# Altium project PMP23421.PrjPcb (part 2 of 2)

## Sheet PMP23421_buffer.SchDoc
size 431 x 279 mm; Date: Not shown in title block; ApprovedBy: Not shown in title block; CheckedBy: Not shown in title block; Author: Not shown in title block; CompanyName: Not shown in title block; Engineer: Not shown in title block; Organization: Not shown in title block; Address1: Not shown in title block; Address2: Not shown in title block; Address3: Not shown in title block; Address4: Not shown in title block; DocumentNumber: 3; Revision: Use project parameter SCH_Rev; SheetNumber: 3; SheetTotal: 3; PageSetup: Record=PageOptions¦CenterHorizontal=True¦CenterVertical=True¦PrintScale=1.00¦XCorrection=1.00¦YCorrection=1.00¦PrintKind=0¦BorderSize=5000000¦LeftOffset=0¦BottomOffset=0¦Orientation=2¦PaperLength=1000¦PaperWidth=1000¦Scale=100¦PaperSource=15¦PrintQuality=600¦MediaType=1¦DitherType=10¦PaperKind=Letter¦PrintScaleMode=1
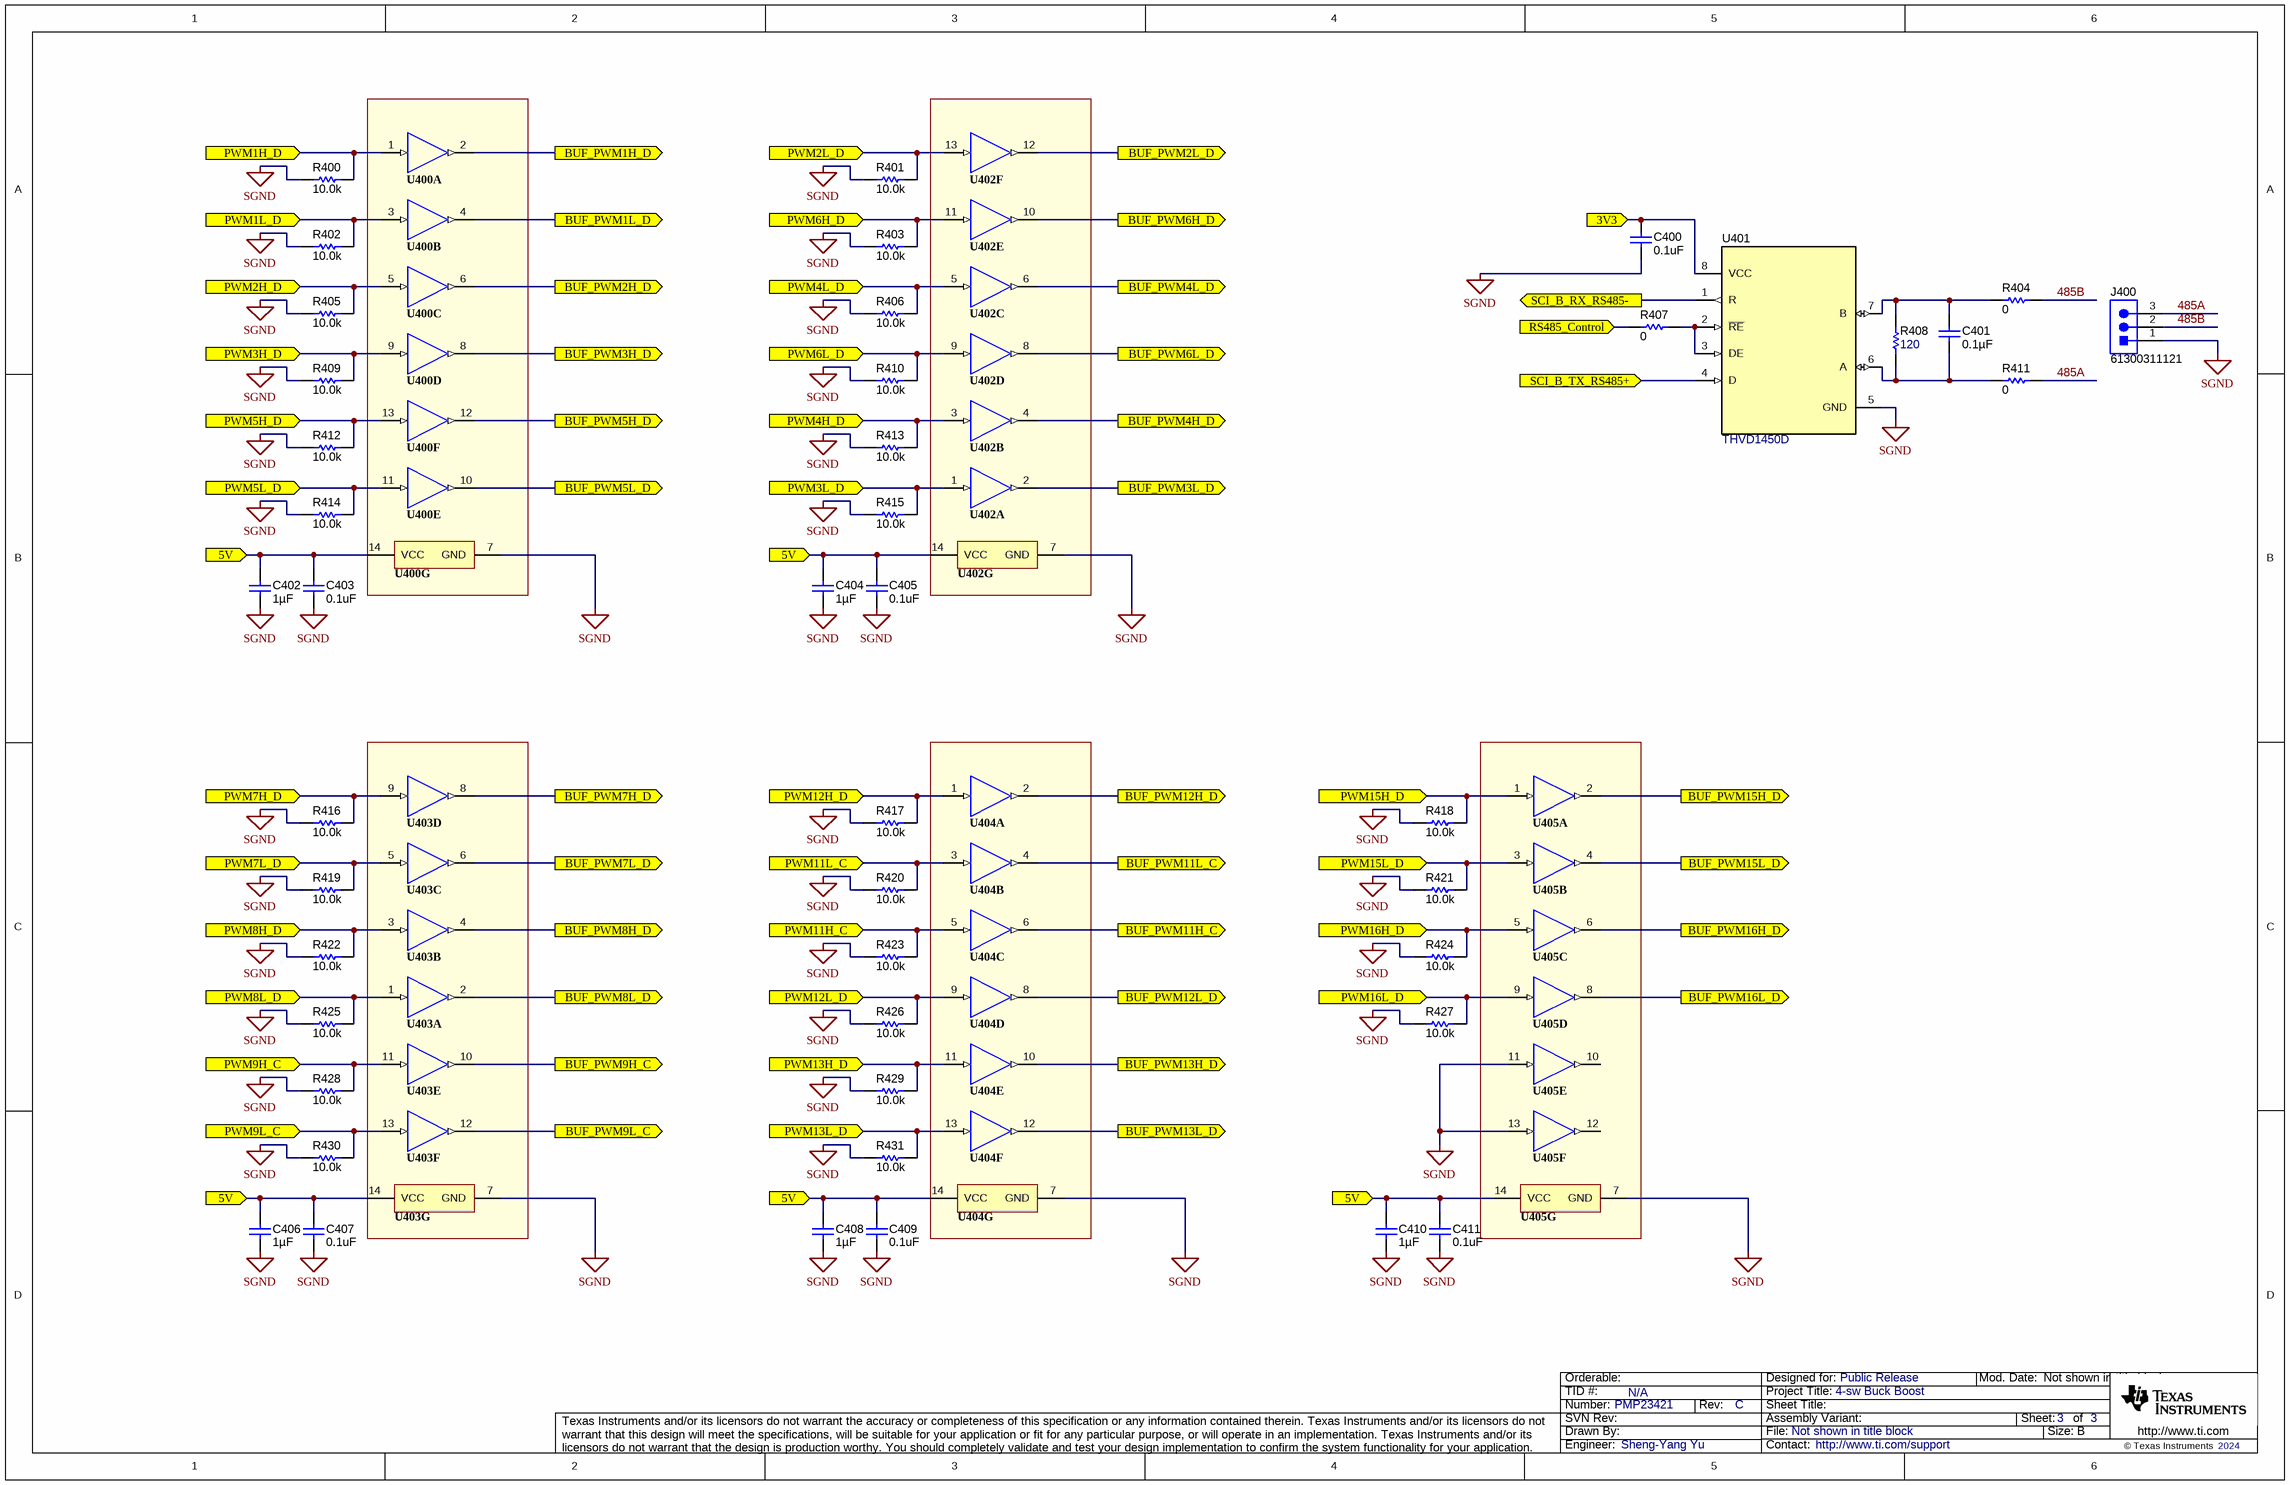
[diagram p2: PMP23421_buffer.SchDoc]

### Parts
(Parts that share a designator on the sheet are numbered #1, #2 ... from top to bottom, then left to right.)
C400  ValueDisplayed: 0.1uF  [0402]  (hidden comment: GRM155R70J104KA01D)
C401  ValueDisplayed: 0.1µF  [1206]  (hidden comment: 12061C104JAT2A)
C402  ValueDisplayed: 1µF  [0603]  (hidden comment: C1608X7R1C105K080AC)
C403  ValueDisplayed: 0.1uF  [0402]  (hidden comment: GRM155R70J104KA01D)
C404  ValueDisplayed: 1µF  [0603]  (hidden comment: C1608X7R1C105K080AC)
C405  ValueDisplayed: 0.1uF  [0402]  (hidden comment: GRM155R70J104KA01D)
C406  ValueDisplayed: 1µF  [0603]  (hidden comment: C1608X7R1C105K080AC)
C407  ValueDisplayed: 0.1uF  [0402]  (hidden comment: GRM155R70J104KA01D)
C408  ValueDisplayed: 1µF  [0603]  (hidden comment: C1608X7R1C105K080AC)
C409  ValueDisplayed: 0.1uF  [0402]  (hidden comment: GRM155R70J104KA01D)
C410  ValueDisplayed: 1µF  [0603]  (hidden comment: C1608X7R1C105K080AC)
C411  ValueDisplayed: 0.1uF  [0402]  (hidden comment: GRM155R70J104KA01D)
J400  61300311121  [WURTH_61300311121]
R400  ValueDisplayed: 10.0k  [0603]  (hidden comment: RCG060310K0FKEA)
R401  ValueDisplayed: 10.0k  [0603]  (hidden comment: RCG060310K0FKEA)
R402  ValueDisplayed: 10.0k  [0603]  (hidden comment: RCG060310K0FKEA)
R403  ValueDisplayed: 10.0k  [0603]  (hidden comment: RCG060310K0FKEA)
R404  ValueDisplayed: 0  [0603]  (hidden comment: RC0603JR-070RL)
R405  ValueDisplayed: 10.0k  [0603]  (hidden comment: RCG060310K0FKEA)
R406  ValueDisplayed: 10.0k  [0603]  (hidden comment: RCG060310K0FKEA)
R407  ValueDisplayed: 0  [0603]  (hidden comment: RC0603JR-070RL)
R408  ValueDisplayed: 120  [0603]  (hidden comment: RC0603FR-07120RL)
R409  ValueDisplayed: 10.0k  [0603]  (hidden comment: RCG060310K0FKEA)
R410  ValueDisplayed: 10.0k  [0603]  (hidden comment: RCG060310K0FKEA)
R411  ValueDisplayed: 0  [0603]  (hidden comment: RC0603JR-070RL)
R412  ValueDisplayed: 10.0k  [0603]  (hidden comment: RCG060310K0FKEA)
R413  ValueDisplayed: 10.0k  [0603]  (hidden comment: RCG060310K0FKEA)
R414  ValueDisplayed: 10.0k  [0603]  (hidden comment: RCG060310K0FKEA)
R415  ValueDisplayed: 10.0k  [0603]  (hidden comment: RCG060310K0FKEA)
R416  ValueDisplayed: 10.0k  [0603]  (hidden comment: RCG060310K0FKEA)
R417  ValueDisplayed: 10.0k  [0603]  (hidden comment: RCG060310K0FKEA)
R418  ValueDisplayed: 10.0k  [0603]  (hidden comment: RCG060310K0FKEA)
R419  ValueDisplayed: 10.0k  [0603]  (hidden comment: RCG060310K0FKEA)
R420  ValueDisplayed: 10.0k  [0603]  (hidden comment: RCG060310K0FKEA)
R421  ValueDisplayed: 10.0k  [0603]  (hidden comment: RCG060310K0FKEA)
R422  ValueDisplayed: 10.0k  [0603]  (hidden comment: RCG060310K0FKEA)
R423  ValueDisplayed: 10.0k  [0603]  (hidden comment: RCG060310K0FKEA)
R424  ValueDisplayed: 10.0k  [0603]  (hidden comment: RCG060310K0FKEA)
R425  ValueDisplayed: 10.0k  [0603]  (hidden comment: RCG060310K0FKEA)
R426  ValueDisplayed: 10.0k  [0603]  (hidden comment: RCG060310K0FKEA)
R427  ValueDisplayed: 10.0k  [0603]  (hidden comment: RCG060310K0FKEA)
R428  ValueDisplayed: 10.0k  [0603]  (hidden comment: RCG060310K0FKEA)
R429  ValueDisplayed: 10.0k  [0603]  (hidden comment: RCG060310K0FKEA)
R430  ValueDisplayed: 10.0k  [0603]  (hidden comment: RCG060310K0FKEA)
R431  ValueDisplayed: 10.0k  [0603]  (hidden comment: RCG060310K0FKEA)
U400  SN74ALS1034D  [D0014A_L]  (value not drawn)  (parts A,B,C,D,E,F,G of 7)
U401  THVD1450D  [D0008A_N]
U402#1  SN74ALS1034D  [D0014A_L]  (value not drawn)  (part F of 7)
U402#2  SN74ALS1034D  [D0014A_L]  (value not drawn)  (parts A,B,C,D,E,G of 7)
U403#1  SN74ALS1034D  [D0014A_L]  (value not drawn)  (parts B,F of 7)
U403#2  SN74ALS1034D  [D0014A_L]  (value not drawn)  (parts A,C,D,E,G of 7)
U404#1  SN74ALS1034D  [D0014A_L]  (value not drawn)  (parts B,E of 7)
U404#2  SN74ALS1034D  [D0014A_L]  (value not drawn)  (parts A,C,D,F,G of 7)
U405#1  SN74ALS1034D  [D0014A_L]  (value not drawn)  (parts B,C,E,F of 7)
U405#2  SN74ALS1034D  [D0014A_L]  (value not drawn)  (parts A,D,G of 7)

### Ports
3V3 (in), 5V (in), BUF_PWM1H_D (out), BUF_PWM1L_D (out), BUF_PWM2H_D (out), BUF_PWM2L_D (out), BUF_PWM3H_D (out), BUF_PWM3L_D (out), BUF_PWM4H_D (out), BUF_PWM4L_D (out), BUF_PWM5H_D (out), BUF_PWM5L_D (out), BUF_PWM6H_D (out), BUF_PWM6L_D (out), BUF_PWM7H_D (out), BUF_PWM7L_D (out), BUF_PWM8H_D (out), BUF_PWM8L_D (out), BUF_PWM9H_C (out), BUF_PWM9L_C (out), BUF_PWM11H_C (out), BUF_PWM11L_C (out), BUF_PWM12H_D (out), BUF_PWM12L_D (out), BUF_PWM13H_D (out), BUF_PWM13L_D (out), BUF_PWM15H_D (out), BUF_PWM15L_D (out), BUF_PWM16H_D (out), BUF_PWM16L_D (out), PWM1H_D (in), PWM1L_D (in), PWM2H_D (in), PWM2L_D (in), PWM3H_D (in), PWM3L_D (in), PWM4H_D (in), PWM4L_D (in), PWM5H_D (in), PWM5L_D (in), PWM6H_D (in), PWM6L_D (in), PWM7H_D (in), PWM7L_D (in), PWM8H_D (in), PWM8L_D (in), PWM9H_C (in), PWM9L_C (in), PWM11H_C (in), PWM11L_C (in), PWM12H_D (in), PWM12L_D (in), PWM13H_D (in), PWM13L_D (in), PWM15H_D (in), PWM15L_D (in), PWM16H_D (in), PWM16L_D (in), RS485_Control (in), SCI_B_RX_RS485- (out), SCI_B_TX_RS485+ (in)

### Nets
SGND: C400.1 C402.2 C403.1 C404.2 C405.1 C406.2 C407.1 C408.2 C409.1 C410.2 C411.1 J400.1 R400.1 R401.1 R402.1 R403.1 R405.1 R406.1 R409.1 R410.1 R412.1 R413.1 R414.1 R415.1 R416.1 R417.1 R418.1 R419.1 R420.1 R421.1 R422.1 R423.1 R424.1 R425.1 R426.1 R427.1 R428.1 R429.1 R430.1 R431.1 U400.7(GND) U401.5(GND) U402#2.7(GND) U403#2.7(GND) U404#2.7(GND) U405#1.11(5A) U405#1.13(6A) U405#2.7(GND)
3V3: C400.2 U401.8(VCC) ; port 3V3
5V: C402.1 C403.2 C404.1 C405.2 C406.1 C407.2 C408.1 C409.2 C410.1 C411.2 U400.14(VCC) U402#2.14(VCC) U403#2.14(VCC) U404#2.14(VCC) U405#2.14(VCC) ; port 5V
485A: J400.3 R411.2
485B: J400.2 R404.2
BUF_PWM1H_D: U400.2(1Y) ; port BUF_PWM1H_D
BUF_PWM1L_D: U400.4(2Y) ; port BUF_PWM1L_D
BUF_PWM2H_D: U400.6(3Y) ; port BUF_PWM2H_D
BUF_PWM2L_D: U402#1.12(6Y) ; port BUF_PWM2L_D
BUF_PWM3H_D: U400.8(4Y) ; port BUF_PWM3H_D
BUF_PWM3L_D: U402#2.2(1Y) ; port BUF_PWM3L_D
BUF_PWM4H_D: U402#2.4(2Y) ; port BUF_PWM4H_D
BUF_PWM4L_D: U402#2.6(3Y) ; port BUF_PWM4L_D
BUF_PWM5H_D: U400.12(6Y) ; port BUF_PWM5H_D
BUF_PWM5L_D: U400.10(5Y) ; port BUF_PWM5L_D
BUF_PWM6H_D: U402#2.10(5Y) ; port BUF_PWM6H_D
BUF_PWM6L_D: U402#2.8(4Y) ; port BUF_PWM6L_D
BUF_PWM7H_D: U403#2.8(4Y) ; port BUF_PWM7H_D
BUF_PWM7L_D: U403#2.6(3Y) ; port BUF_PWM7L_D
BUF_PWM8H_D: U403#1.4(2Y) ; port BUF_PWM8H_D
BUF_PWM8L_D: U403#2.2(1Y) ; port BUF_PWM8L_D
BUF_PWM9H_C: U403#2.10(5Y) ; port BUF_PWM9H_C
BUF_PWM9L_C: U403#1.12(6Y) ; port BUF_PWM9L_C
BUF_PWM11H_C: U404#2.6(3Y) ; port BUF_PWM11H_C
BUF_PWM11L_C: U404#1.4(2Y) ; port BUF_PWM11L_C
BUF_PWM12H_D: U404#2.2(1Y) ; port BUF_PWM12H_D
BUF_PWM12L_D: U404#2.8(4Y) ; port BUF_PWM12L_D
BUF_PWM13H_D: U404#1.10(5Y) ; port BUF_PWM13H_D
BUF_PWM13L_D: U404#2.12(6Y) ; port BUF_PWM13L_D
BUF_PWM15H_D: U405#2.2(1Y) ; port BUF_PWM15H_D
BUF_PWM15L_D: U405#1.4(2Y) ; port BUF_PWM15L_D
BUF_PWM16H_D: U405#1.6(3Y) ; port BUF_PWM16H_D
BUF_PWM16L_D: U405#2.8(4Y) ; port BUF_PWM16L_D
PWM1H_D: R400.2 U400.1(1A) ; port PWM1H_D
PWM1L_D: R402.2 U400.3(2A) ; port PWM1L_D
PWM2H_D: R405.2 U400.5(3A) ; port PWM2H_D
PWM2L_D: R401.2 U402#1.13(6A) ; port PWM2L_D
PWM3H_D: R409.2 U400.9(4A) ; port PWM3H_D
PWM3L_D: R415.2 U402#2.1(1A) ; port PWM3L_D
PWM4H_D: R413.2 U402#2.3(2A) ; port PWM4H_D
PWM4L_D: R406.2 U402#2.5(3A) ; port PWM4L_D
PWM5H_D: R412.2 U400.13(6A) ; port PWM5H_D
PWM5L_D: R414.2 U400.11(5A) ; port PWM5L_D
PWM6H_D: R403.2 U402#2.11(5A) ; port PWM6H_D
PWM6L_D: R410.2 U402#2.9(4A) ; port PWM6L_D
PWM7H_D: R416.2 U403#2.9(4A) ; port PWM7H_D
PWM7L_D: R419.2 U403#2.5(3A) ; port PWM7L_D
PWM8H_D: R422.2 U403#1.3(2A) ; port PWM8H_D
PWM8L_D: R425.2 U403#2.1(1A) ; port PWM8L_D
PWM9H_C: R428.2 U403#2.11(5A) ; port PWM9H_C
PWM9L_C: R430.2 U403#1.13(6A) ; port PWM9L_C
PWM11H_C: R423.2 U404#2.5(3A) ; port PWM11H_C
PWM11L_C: R420.2 U404#1.3(2A) ; port PWM11L_C
PWM12H_D: R417.2 U404#2.1(1A) ; port PWM12H_D
PWM12L_D: R426.2 U404#2.9(4A) ; port PWM12L_D
PWM13H_D: R429.2 U404#1.11(5A) ; port PWM13H_D
PWM13L_D: R431.2 U404#2.13(6A) ; port PWM13L_D
PWM15H_D: R418.2 U405#2.1(1A) ; port PWM15H_D
PWM15L_D: R421.2 U405#1.3(2A) ; port PWM15L_D
PWM16H_D: R424.2 U405#1.5(3A) ; port PWM16H_D
PWM16L_D: R427.2 U405#2.9(4A) ; port PWM16L_D
RS485_Control: R407.1 ; port RS485_Control
SCI_B_RX_RS485-: U401.1(R) ; port SCI_B_RX_RS485-
SCI_B_TX_RS485+: U401.4(D) ; port SCI_B_TX_RS485+
NetC401_1: C401.1 R404.1 R408.2 U401.7(B)
NetC401_2: C401.2 R408.1 R411.1 U401.6(A)
NetR407_2: R407.2 U401.2(~{RE}) U401.3(DE)

Not connected (* = marked no-connect by the designer): U405#1 10(5Y) 12(6Y)

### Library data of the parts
C400 C403 C405 C407 C409 C411 = GRM155R70J104KA01D: CAP, CERM, 0.1uF, 6.3V, +/-10%, X7R, 0402; Manufacturer: MuRata; Polarized: N; CompType: Capacitor; U/M: EA; Cap_F: 0.0000001; Tolerance_%: 10; Value1: Unknown; VDC_V: 6.3; TaMin_C: -55; TaMax_C: 125
C401 = 12061C104JAT2A: CAP, CERM, 0.1 µF, 100 V,+/- 5%, X7R, 1206; Manufacturer: AVX; Polarized: N; CompType: Capacitor; Value: 0.1uF; U/M: EA; Cap_F: 0.0000001; Tolerance_%: 5; ESR_ohm: 0.037; Value1: 0.037 ohm; VDC_V: 100; Value2: 100V; TaMin_C: -55; TaMax_C: 125; SizeArea_mm2: 5.12; SizeAreaWB_mm2: 10.92; SizeX_mm: 3.2; SizeY_mm: 1.6; SizeZ_mm: 1.35; AEC Category: Q200; Green_Lifecycle: Active; Green_REACh: Passed
C402 C404 C406 C408 C410 = C1608X7R1C105K080AC: CAP, CERM, 1 µF, 16 V,+/- 10%, X7R, 0603; Manufacturer: TDK; Polarized: N; CompType: Capacitor; Value: 1uF; U/M: EA; Cap_F: 0.000001; Tolerance_%: 10; ESR_ohm: 0.0057; Value1: 0.0057 ohm; VDC_V: 16; Value2: 16V; TaMin_C: -55; TaMax_C: 125; SizeArea_mm2: 1.28; SizeAreaWB_mm2: 4.68; SizeX_mm: 1.6; SizeY_mm: 0.8; SizeZ_mm: 1; AEC Category: Q200; Green_Lifecycle: Active; Green_REACh: Passed
J400 = CMP-0054796-4: Header, 2.54 mm, 3x1, Gold, TH; Manufacturer: Wurth Elektronik; Green_REACh: Passed; CT: FALSE; CNHeader: TRUE; Green_Lifecycle: Active
R400-R403 R405 R406 R409 R410 R412-R431 = RCG060310K0FKEA: RES, 10.0 k, 1%, 0.1 W, 0603; Manufacturer: Vishay Draloric; CompType: Resistor; Value: 10.0k; Res_ohm: 10000; Value_Code: 10k0; Tolerance_%: 1; Power_W: 0.1; Value2: 0.1W; VDC_V: 75; TempCo: 100 ppm/C; SizeArea_mm2: 1.28; SizeX_mm: 1.6; SizeY_mm: 0.8; EIA_Code: E96; U/M: EA; AEC Category: Q200; AEC Qualified: N
R404 R407 R411 = RC0603JR-070RL: RES, 0, 5%, 0.1 W, 0603; Manufacturer: Yageo America; CompType: Resistor; Value: 0; Value_Code: 0000; Tolerance_%: 5; Power_W: 0.1; Value2: 0.1W; VDC_V: 50; TempCo: 200 ppm/C; SizeArea_mm2: 1.28; SizeX_mm: 1.6; SizeY_mm: 0.8; SizeZ_mm: 1; EIA_Code: E24; U/M: EA; AEC Category: Q200; Green_Lifecycle: Active; Green_REACh: Passed
R408 = CMP-0022769-5: RES, 120, 1%, 0.1 W, 0603; Manufacturer: Yageo; Power_W: 100mW; TempCo: 100 ppm/C; Value_Code: 120R; Value: 120; SizeX_mm: 1.6; SizeY_mm: 0.8; SizeZ_mm: 1; Value2: 0.1W; SizeArea_mm2: 1.28; AEC Qualified: N; VDC_V: 75V; AEC Category: Q200; SizeAreaWB_mm2: 4.68
U400 U402#1 U402#2 U403#1 U403#2 U404#1 U404#2 U405#1 U405#2 = CMP-0047016-1: Hex Noninverting Drivers, D0014A, TUBE; Manufacturer: Texas Instruments; Voltage(Nom)(V): 5; ICC @ Nom Voltage(Max)(mA): 0.014; tpd @ Nom Voltage(Max)(ns): 8; Input Type: TTL; Bits(#): 6; VCC(Max)(V): 5.5; VCC(Min)(V): 4.5; Rating: Catalog; F @ Nom Voltage(Max)(Mhz): 75
U401 = CMP-0065059-3: 3.3-V to 5-V RS-485 Transceivers With +/-18-kV IEC ESD Protection, D0008A (SOIC-8); Manufacturer: Texas Instruments; Alternate PartNumber: THVD1450DR; SizeX_mm: 4.9; SizeY_mm: 6.2; CompType: IC; SizeZ_mm: 1.75; SizeArea_mm2: 30.38; SizeAreaWB_mm2: 56.58; AEC Category: Q200; AEC Qualified: N

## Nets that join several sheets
SGND: PMP23421_Control (58 pins), PMP23421_ORING_N_CS (51 pins), PMP23421_buffer (48 pins)
3V3: PMP23421_Control (7 pins), PMP23421_buffer (C400.2 U401.8)
5V: PMP23421_Control (14 pins), PMP23421_ORING_N_CS (7 pins), PMP23421_buffer (15 pins)
12V: PMP23421_Control (5 pins), PMP23421_ORING_N_CS (7 pins)
48VOUT1: PMP23421_Control (R203.2 R226.2), PMP23421_ORING_N_CS (19 pins)
48VOUT2: PMP23421_Control (R204.2), PMP23421_ORING_N_CS (9 pins)
BUF_PWM1H_D: PMP23421_ORING_N_CS (J300.1), PMP23421_buffer (U400.2)
BUF_PWM1L_D: PMP23421_ORING_N_CS (J300.3), PMP23421_buffer (U400.4)
BUF_PWM2H_D: PMP23421_ORING_N_CS (J300.9), PMP23421_buffer (U400.6)
BUF_PWM2L_D: PMP23421_ORING_N_CS (J300.11), PMP23421_buffer (U402#1.12)
BUF_PWM3H_D: PMP23421_ORING_N_CS (J301.1), PMP23421_buffer (U400.8)
BUF_PWM3L_D: PMP23421_ORING_N_CS (J301.3), PMP23421_buffer (U402#2.2)
BUF_PWM4H_D: PMP23421_ORING_N_CS (J301.9), PMP23421_buffer (U402#2.4)
BUF_PWM4L_D: PMP23421_ORING_N_CS (J301.11), PMP23421_buffer (U402#2.6)
BUF_PWM5H_D: PMP23421_ORING_N_CS (J302.1), PMP23421_buffer (U400.12)
BUF_PWM5L_D: PMP23421_ORING_N_CS (J302.3), PMP23421_buffer (U400.10)
BUF_PWM6H_D: PMP23421_ORING_N_CS (J302.9), PMP23421_buffer (U402#2.10)
BUF_PWM6L_D: PMP23421_ORING_N_CS (J302.11), PMP23421_buffer (U402#2.8)
BUF_PWM7H_D: PMP23421_ORING_N_CS (J303.1), PMP23421_buffer (U403#2.8)
BUF_PWM7L_D: PMP23421_ORING_N_CS (J303.3), PMP23421_buffer (U403#2.6)
BUF_PWM8H_D: PMP23421_ORING_N_CS (J303.9), PMP23421_buffer (U403#1.4)
BUF_PWM8L_D: PMP23421_ORING_N_CS (J303.11), PMP23421_buffer (U403#2.2)
BUF_PWM9H_C: PMP23421_ORING_N_CS (J306.1), PMP23421_buffer (U403#2.10)
BUF_PWM9L_C: PMP23421_ORING_N_CS (J306.3), PMP23421_buffer (U403#1.12)
BUF_PWM11H_C: PMP23421_ORING_N_CS (J306.9), PMP23421_buffer (U404#2.6)
BUF_PWM11L_C: PMP23421_ORING_N_CS (J306.11), PMP23421_buffer (U404#1.4)
BUF_PWM12H_D: PMP23421_ORING_N_CS (J304.1), PMP23421_buffer (U404#2.2)
BUF_PWM12L_D: PMP23421_ORING_N_CS (J304.3), PMP23421_buffer (U404#2.8)
BUF_PWM13H_D: PMP23421_ORING_N_CS (J304.9), PMP23421_buffer (U404#1.10)
BUF_PWM13L_D: PMP23421_ORING_N_CS (J304.11), PMP23421_buffer (U404#2.12)
BUF_PWM15H_D: PMP23421_ORING_N_CS (J305.1), PMP23421_buffer (U405#2.2)
BUF_PWM15L_D: PMP23421_ORING_N_CS (J305.3), PMP23421_buffer (U405#1.4)
BUF_PWM16H_D: PMP23421_ORING_N_CS (J305.9), PMP23421_buffer (U405#1.6)
BUF_PWM16L_D: PMP23421_ORING_N_CS (J305.11), PMP23421_buffer (U405#2.8)
CS+_total_charge_current_battery: PMP23421_Control (R202.2 R230.2), PMP23421_ORING_N_CS (6 pins)
CS-_total_charge_current_battery: PMP23421_Control (R201.2 R232.2), PMP23421_ORING_N_CS (20 pins)
CS-_total_discharge_current_bus: PMP23421_Control (R228.2), PMP23421_ORING_N_CS (6 pins)
ICS_1ph: PMP23421_Control (R200.1), PMP23421_ORING_N_CS (J300.5)
ICS_2ph: PMP23421_Control (R205.1), PMP23421_ORING_N_CS (J301.5)
ICS_3ph: PMP23421_Control (R206.2), PMP23421_ORING_N_CS (J302.5)
ICS_4ph: PMP23421_Control (R213.1), PMP23421_ORING_N_CS (J303.5)
ICS_5ph: PMP23421_Control (R207.2), PMP23421_ORING_N_CS (J304.5)
ICS_6ph: PMP23421_Control (R212.2), PMP23421_ORING_N_CS (J305.5)
ICS_7ph: PMP23421_Control (R218.1), PMP23421_ORING_N_CS (J306.5)
ORING_CONTROL: PMP23421_Control (J200.88), PMP23421_ORING_N_CS (U300.3)
PWM1H_D: PMP23421_Control (J200.49), PMP23421_buffer (R400.2 U400.1)
PWM1L_D: PMP23421_Control (J200.51), PMP23421_buffer (R402.2 U400.3)
PWM2H_D: PMP23421_Control (J200.53), PMP23421_buffer (R405.2 U400.5)
PWM2L_D: PMP23421_Control (J200.55), PMP23421_buffer (R401.2 U402#1.13)
PWM3H_D: PMP23421_Control (J200.50), PMP23421_buffer (R409.2 U400.9)
PWM3L_D: PMP23421_Control (J200.52), PMP23421_buffer (R415.2 U402#2.1)
PWM4H_D: PMP23421_Control (J200.54), PMP23421_buffer (R413.2 U402#2.3)
PWM4L_D: PMP23421_Control (J200.56), PMP23421_buffer (R406.2 U402#2.5)
PWM5H_D: PMP23421_Control (J200.57), PMP23421_buffer (R412.2 U400.13)
PWM5L_D: PMP23421_Control (J200.59), PMP23421_buffer (R414.2 U400.11)
PWM6H_D: PMP23421_Control (J200.61), PMP23421_buffer (R403.2 U402#2.11)
PWM6L_D: PMP23421_Control (J200.63), PMP23421_buffer (R410.2 U402#2.9)
PWM7H_D: PMP23421_Control (J200.58), PMP23421_buffer (R416.2 U403#2.9)
PWM7L_D: PMP23421_Control (J200.60), PMP23421_buffer (R419.2 U403#2.5)
PWM8H_D: PMP23421_Control (J200.62), PMP23421_buffer (R422.2 U403#1.3)
PWM8L_D: PMP23421_Control (J200.64), PMP23421_buffer (R425.2 U403#2.1)
PWM9H_C: PMP23421_Control (J200.67), PMP23421_buffer (R428.2 U403#2.11)
PWM9L_C: PMP23421_Control (J200.69), PMP23421_buffer (R430.2 U403#1.13)
PWM11H_C: PMP23421_Control (J200.68), PMP23421_buffer (R423.2 U404#2.5)
PWM11L_C: PMP23421_Control (J200.70), PMP23421_buffer (R420.2 U404#1.3)
PWM12H_D: PMP23421_Control (J200.72), PMP23421_buffer (R417.2 U404#2.1)
PWM12L_D: PMP23421_Control (J200.74), PMP23421_buffer (R426.2 U404#2.9)
PWM13H_D: PMP23421_Control (J200.75), PMP23421_buffer (R429.2 U404#1.11)
PWM13L_D: PMP23421_Control (J200.77), PMP23421_buffer (R431.2 U404#2.13)
PWM15H_D: PMP23421_Control (J202.156), PMP23421_buffer (R418.2 U405#2.1)
PWM15L_D: PMP23421_Control (J202.159), PMP23421_buffer (R421.2 U405#1.3)
PWM16H_D: PMP23421_Control (J202.160), PMP23421_buffer (R424.2 U405#1.5)
PWM16L_D: PMP23421_Control (J202.161), PMP23421_buffer (R427.2 U405#2.9)
RS485_Control: PMP23421_Control (J200.99), PMP23421_buffer (R407.1)
SCI_B_RX_RS485-: PMP23421_Control (J200.102), PMP23421_buffer (U401.1)
SCI_B_TX_RS485+: PMP23421_Control (J200.100), PMP23421_buffer (U401.4)

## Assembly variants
001: not fitted Q300 Q301 Q302 U300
